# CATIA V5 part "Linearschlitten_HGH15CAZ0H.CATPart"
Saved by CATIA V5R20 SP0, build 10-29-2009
Part number: Linearschlitten_HGH15CAZ0H
Source: Unknown
Description: PART--DESC
Bounding box of the stored display mesh (mm): x -17 to 17, y -6.489 to 63.073, z 4.3 to 28
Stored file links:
  C:\Users\Andi\Desktop\Plasma\Linearschlitten_HGH15CAZ0H.CATPart
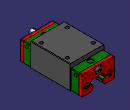
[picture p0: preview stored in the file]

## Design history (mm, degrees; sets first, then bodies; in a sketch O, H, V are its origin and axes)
Body1 "HGH15CAZ0H_FILE" (main body)
  Solid1: solid without history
